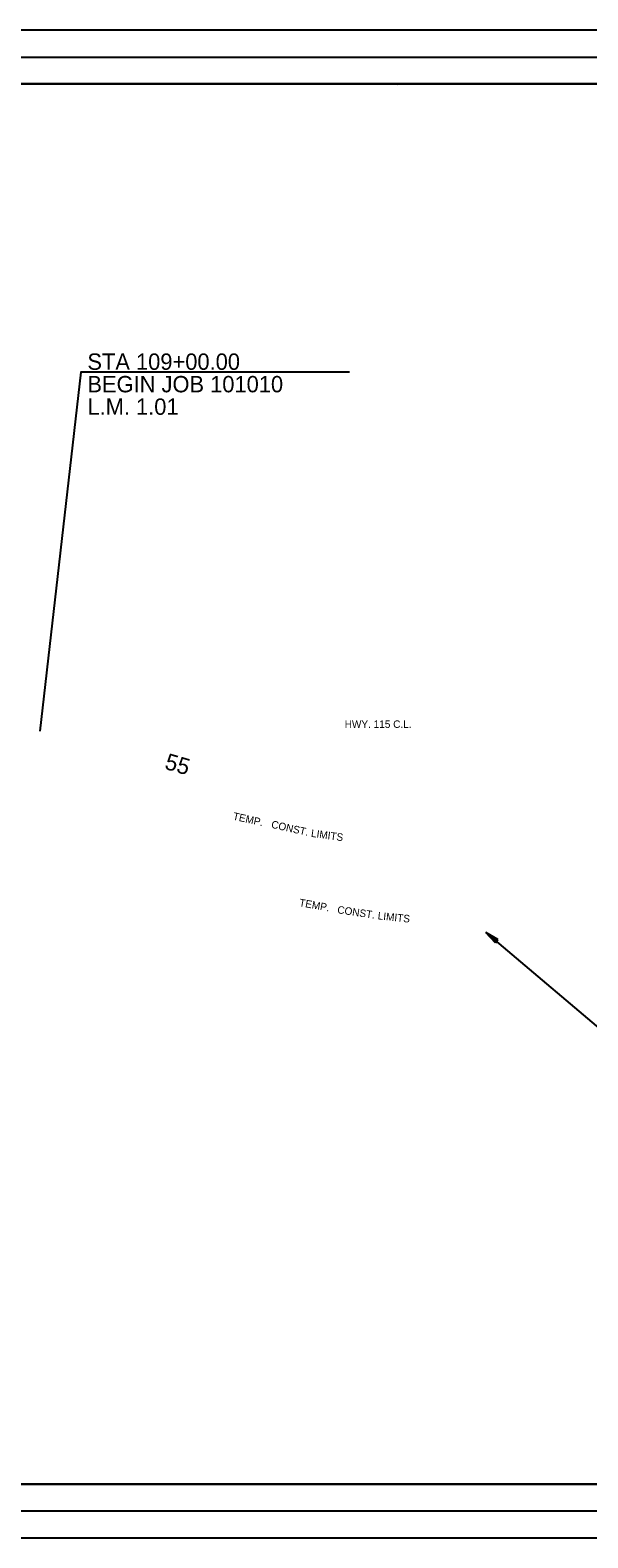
# Model space of a CAD drawing. Extents: x 9525 to 11605, y 9961 to 11067.
# Drawn here: x 10493 to 10902, y 9961 to 11067 of the extents above; entities that cross this region are included whole.
import ezdxf

# ---------------------------------------------------------------- set-up
doc = ezdxf.new("R2010")
doc.units = 0
for name, color, linetype in [('Clearing and Grubbing Temp Seeding', 7, 'Continuous'), ('GREEN_TXT', 7, 'Continuous'), ('R_Draft', 7, 'Continuous'), ('SEAL-INFO', 7, 'Continuous'), ('Stage 1 Construction', 7, 'Continuous'), ('Stage 1 Ditch Checks', 7, 'Continuous'), ('Stage 3 Seeding MAIN', 7, 'Continuous')]:
    doc.layers.add(name, color=color, linetype=linetype)

msp = doc.modelspace()

# ---------------------------------------------------------------- linework, layer by layer
at = {"layer": 'GREEN_TXT'}
for p, q in [((11603.9, 11066.7), (9843.9, 11066.7)), ((10000, 11027.3), (11580.9, 11027.3)), ((10762.6, 11026), (10762.6, 11026)), ((10762.6, 11026), (10762.6, 11026)), ((11580.9, 10000), (10000, 10000)), ((9843.9, 9960.6), (11603.9, 9960.6))]:
    msp.add_line(p, q, dxfattribs=at)
at = {"layer": 'SEAL-INFO'}
msp.add_lwpolyline([(9938, 11046.8), (11604.7, 11046.8), (11604.7, 9980.1), (9938, 9980.1)], close=True, dxfattribs=at)
at = {"layer": 'Stage 1 Construction'}
msp.add_lwpolyline([(10727.2, 10815.9), (10530.2, 10815.9), (10500, 10552.4)], dxfattribs=at)
at = {"layer": 'Stage 1 Ditch Checks'}
msp.add_lwpolyline([(10000, 10000), (11580.9, 10000), (11580.3, 10963.3), (11365.4, 10963.3), (11357.3, 10959.9), (11348.5, 10961.4), (11348.3, 10977.9), (11169.6, 10977.9), (11169.6, 11027.3), (10000, 11027.3)], close=True, dxfattribs=at)
msp.add_lwpolyline([(10000, 10000), (11580.9, 10000), (11580.3, 10963.3), (11365.4, 10963.3), (11357.3, 10959.9), (11348.5, 10961.4), (11348.3, 10977.9), (11169.6, 10977.9), (11169.6, 11027.3), (10000, 11027.3)], close=True, dxfattribs=at)
at = {"layer": 'Stage 3 Seeding MAIN'}
for p, q in [((10827.4, 10404.6), (11001.1, 10257.5)), ((10834.4, 10397.2), (10827.4, 10404.6)), ((10836.2, 10399.6), (10827.4, 10404.6)), ((10834.5, 10397.4), (10828.8, 10403.6)), ((10836.1, 10399.4), (10828.8, 10403.6)), ((10835.9, 10399.2), (10830.1, 10402.5)), ((10834.7, 10397.6), (10830.1, 10402.5)), ((10834.9, 10397.8), (10831.4, 10401.5)), ((10835.8, 10399), (10831.4, 10401.5)), ((10835.6, 10398.8), (10832.8, 10400.4)), ((10835, 10398), (10832.8, 10400.4)), ((10835.5, 10398.6), (10834.1, 10399.4)), ((10835.2, 10398.2), (10834.1, 10399.4)), ((10834.4, 10397.2), (10836.2, 10399.6))]:
    msp.add_line(p, q, dxfattribs=at)

# ---------------------------------------------------------------- texts
at = {"layer": 'Clearing and Grubbing Temp Seeding'}
for s, rotation, p in [('TEMP. ', 347.2879, (10641.4, 10487.6)), ('CONST. ', 347.3655, (10669.5, 10481.6)), (' LIMITS', 352.147, (10696.8, 10475.2)), ('TEMP. ', 349.8256, (10690.1, 10424.1)), ('CONST. ', 351.4475, (10718.1, 10418.9)), (' LIMITS', 354.0544, (10745.8, 10414.6))]:
    msp.add_text(s, height=5.5, rotation=rotation, dxfattribs=at).set_placement(p)
at = {"layer": 'R_Draft'}
msp.add_text('55', height=12, rotation=343.9098, dxfattribs=at).set_placement((10591, 10524.9))
at = {"layer": 'Stage 1 Construction'}
for s, p in [('STA 109+00.00', (10535, 10817.5)), ('BEGIN JOB 101010', (10535, 10801)), ('L.M. 1.01', (10535, 10784.5))]:
    msp.add_text(s, height=12, dxfattribs=at).set_placement(p)
at = {"layer": 'Stage 3 Seeding MAIN'}
msp.add_text('HWY. 115 C.L.', height=5.5, dxfattribs=at).set_placement((10723.8, 10554.8))

doc.saveas('drawing.dxf')
